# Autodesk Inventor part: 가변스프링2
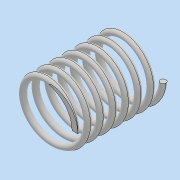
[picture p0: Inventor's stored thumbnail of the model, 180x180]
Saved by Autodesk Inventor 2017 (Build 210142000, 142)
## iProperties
Part Number: 가변스프링2
Material: 일반
Document SubType Name: Modeling
Designer: MRC
Density: 1 g/cm^3
Appearance: 기본값
Author: MRC
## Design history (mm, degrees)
sketch "스케치1"
  geometry: L1 (0, 30.358)-(10, 30.358); L2 (10, 30.358)-(10, 0); L3 (10, 0)-(0, 0); L4 (0, 0)-(0, 30.358); C1 r 1 at (10, 0); 1 further point
  constraints: 8 end point, 2 coincident, 2 parallel, 1 centre point, 1 horizontal, 1 perpendicular
  dimensions: "d0" = 30.35829 distance of L1.end L2.end (derived); "d1" = 20 diameter of L2 L4; "d2" = 2 diameter of C1
feature "코일1" sketch "스케치1" pitch "d3" = 10; turns "d5" = 7; dims "d4" = 30.35829 (= d0), "d6" = 0, angle "d7" = 90 deg, angle "d8" = 90 deg, "d9" = 0, "d10" = 0
sketch "스케치2"
  geometry: L1 (-19.444, 50)-(19.444, 50); L2 (19.444, 50)-(19.444, 0); L3 (19.444, 0)-(-19.444, 0); L4 (-19.444, 0)-(-19.444, 50); 2 further points
  constraints: 8 end point, 2 parallel, 1 coincident, 1 horizontal, 1 midpoint, 1 perpendicular
  dimensions: "d11" = 50 distance of L1.end L2.end; "d12" = 38.88889 distance of L1.start L1.end
extrude "돌출1" sketch "스케치2" stored distance "d13" = 0; taper "d14" = 0 deg
node "솔리드1"
